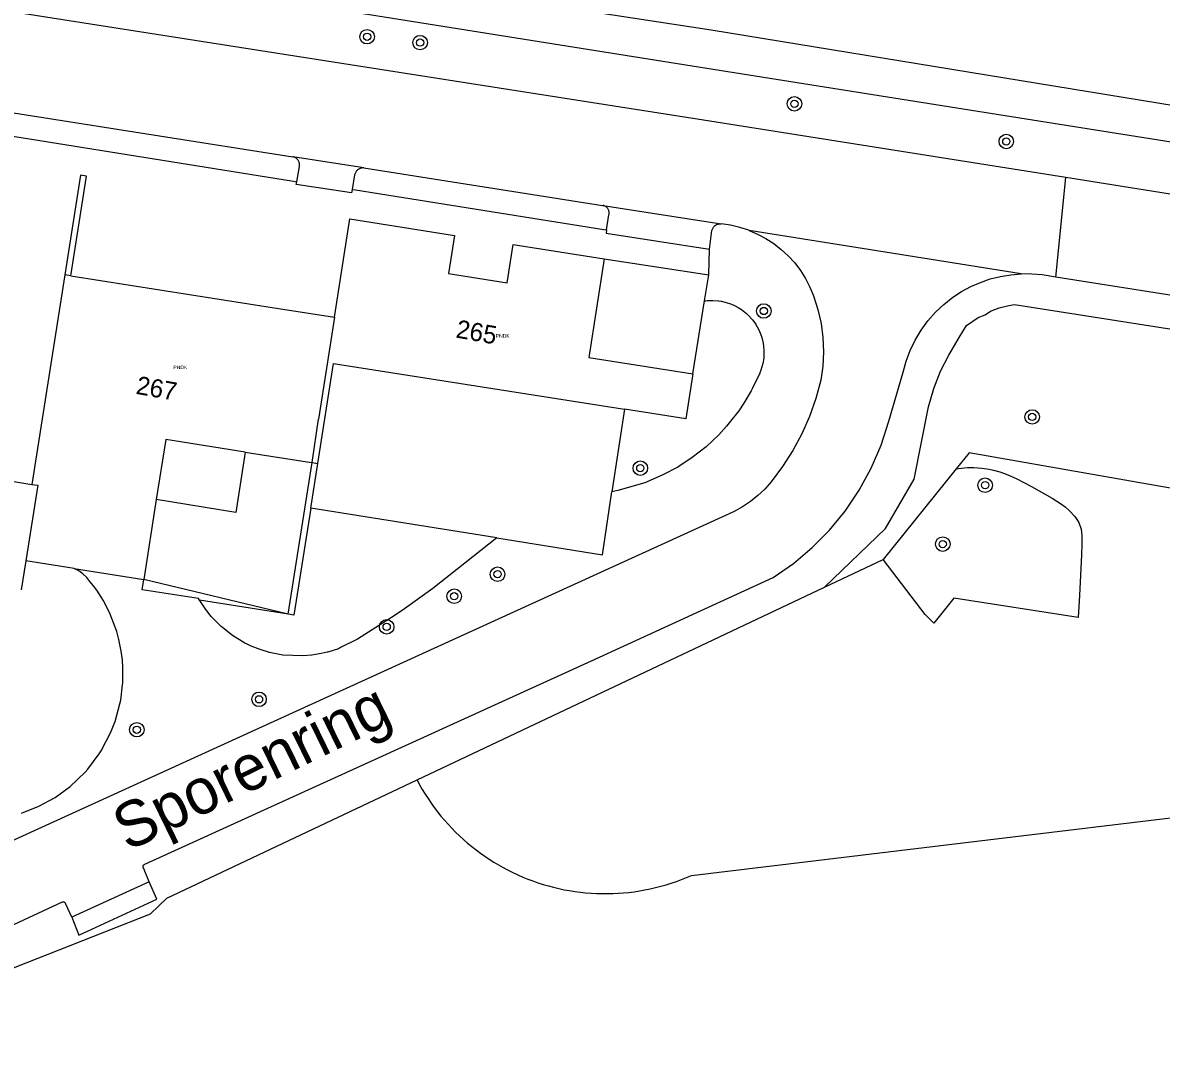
# Model space of a CAD drawing. Extents: x 131000 to 133013, y 393000 to 396501.
# Drawn here: x 132762.8 to 132825.5, y 394210.9 to 394268.4 of the extents above; entities that cross this region are included whole.
import ezdxf

# ---------------------------------------------------------------- set-up
doc = ezdxf.new("R2010")
doc.units = 0
for name, color, linetype in [('gg-anno-huisnummerreeks BGT', 7, 'Continuous'), ('gg-anno-openbare ruimte label', 7, 'Continuous'), ('gg-kwrk-kunstwerk niveau 01', 7, 'Continuous'), ('gt-symb-boom', 7, 'Continuous'), ('gx-grn-maaiveld', 7, 'Continuous'), ('kenmerkpunt-x pandkandidaat', 7, 'Continuous')]:
    doc.layers.add(name, color=color, linetype=linetype)

# ---------------------------------------------------------------- blocks, each defined once
blk = doc.blocks.new('gt0-BOOM')
at = {"layer": 'gt-symb-boom'}
for radius in [0.4, 0.2]:
    blk.add_circle((0, 0), radius, dxfattribs=at)

msp = doc.modelspace()

# ---------------------------------------------------------------- linework, layer by layer
at = {"layer": 'gg-kwrk-kunstwerk niveau 01'}
for p, q in [((132794.792, 394255.438), (132800.552, 394254.557)), ((132800.32, 394253.123), (132800.552, 394254.557)), ((132799.667, 394249.103), (132800.32, 394253.123))]:
    msp.add_line(p, q, dxfattribs=at)
for points in [[(132794.792, 394255.438), (132793.937, 394250.005), (132799.667, 394249.103)], [(132775.023, 394244.803), (132770.646, 394245.492), (132770.126, 394242.182)], [(132775.023, 394244.803), (132774.501, 394241.467), (132770.126, 394242.182)]]:
    msp.add_lwpolyline(points, dxfattribs=at)
at = {"layer": 'gx-grn-maaiveld'}
for p, q in [((132762.259, 394263.486), (132777.637, 394261.067)), ((132781.55, 394260.446), (132777.637, 394261.067)), ((132819.657, 394254.437), (132820.212, 394259.915)), ((132826.299, 394258.951), (132820.212, 394259.915)), ((132794.732, 394258.378), (132801.231, 394257.37)), ((132817.752, 394254.61), (132802.765, 394257.008)), ((132800.552, 394254.557), (132800.58, 394255.973)), ((132765.095, 394254.562), (132763.28, 394243.024)), ((132765.411, 394254.513), (132765.095, 394254.562)), ((132830.081, 394252.795), (132819.657, 394254.437)), ((132779.933, 394252.228), (132779.05, 394246.617)), ((132795.91, 394247.166), (132795.217, 394242.621)), ((132778.704, 394244.224), (132779.05, 394246.617)), ((132756.355, 394244.114), (132763.28, 394243.024)), ((132777.391, 394235.877), (132778.704, 394244.224)), ((132778.633, 394241.715), (132779.02, 394244.175)), ((132778.704, 394244.224), (132779.02, 394244.175)), ((132814.179, 394243.879), (132810.154, 394238.888)), ((132770.126, 394242.182), (132769.435, 394237.793)), ((132788.877, 394240.077), (132778.633, 394241.715)), ((132762.935, 394238.816), (132762.683, 394237.216)), ((132765.604, 394238.396), (132762.935, 394238.816)), ((132806.928, 394237.362), (132810.154, 394238.888)), ((132765.604, 394238.396), (132769.435, 394237.793)), ((132777.391, 394235.877), (132769.435, 394237.793)), ((132784.483, 394226.745), (132806.928, 394237.362)), ((132777.391, 394235.877), (132772.501, 394236.65)), ((132769.739, 394221.139), (132765.469, 394219.187))]:
    msp.add_line(p, q, dxfattribs=at)
for points in [[(132756.624, 394274.795), (132800.677, 394268.056), (132833.81, 394262.63)], [(132827.168, 394261.677), (132800.437, 394265.921), (132762.945, 394271.904)], [(132820.212, 394259.915), (132799.908, 394263.131), (132762.861, 394268.939)], [(132761.631, 394262.295), (132761.775, 394262.271), (132777.688, 394259.717), (132777.861, 394259.686)], [(132777.861, 394259.686), (132778.015, 394260.533), (132778.019, 394260.573), (132778.019, 394260.612), (132778.017, 394260.652), (132778.01, 394260.692), (132778.001, 394260.73), (132777.988, 394260.768), (132777.973, 394260.805), (132777.954, 394260.84), (132777.932, 394260.873), (132777.908, 394260.905), (132777.881, 394260.935), (132777.851, 394260.962), (132777.82, 394260.987), (132777.786, 394261.009), (132777.751, 394261.028), (132777.714, 394261.044), (132777.676, 394261.057), (132777.637, 394261.067)], [(132765.411, 394254.513), (132766.274, 394259.995), (132765.958, 394260.045), (132765.095, 394254.562)], [(132781.55, 394260.446), (132781.509, 394260.448), (132781.469, 394260.446), (132781.429, 394260.44), (132781.389, 394260.432), (132781.35, 394260.419), (132781.313, 394260.404), (132781.277, 394260.385), (132781.242, 394260.364), (132781.21, 394260.339), (132781.18, 394260.312), (132781.152, 394260.283), (132781.127, 394260.252), (132781.105, 394260.218), (132781.086, 394260.183), (132781.07, 394260.146), (132781.057, 394260.108), (132781.047, 394260.069), (132780.91, 394259.267)], [(132781.55, 394260.446), (132794.697, 394258.384), (132794.732, 394258.378)], [(132780.91, 394259.267), (132780.877, 394259.071), (132777.835, 394259.54), (132777.861, 394259.686)], [(132780.91, 394259.267), (132781.093, 394259.234), (132794.766, 394257.055), (132794.916, 394257.03)], [(132794.916, 394257.03), (132795.045, 394257.861), (132795.054, 394257.895), (132795.059, 394257.93), (132795.062, 394257.966), (132795.061, 394258.001), (132795.058, 394258.036), (132795.051, 394258.071), (132795.042, 394258.105), (132795.029, 394258.138), (132795.014, 394258.17), (132794.996, 394258.201), (132794.974, 394258.231), (132794.951, 394258.258), (132794.925, 394258.283), (132794.896, 394258.306), (132794.866, 394258.326), (132794.835, 394258.343), (132794.802, 394258.358), (132794.767, 394258.37), (132794.732, 394258.378)], [(132779.933, 394252.228), (132780.784, 394257.641), (132786.544, 394256.735), (132786.213, 394254.631), (132789.453, 394254.122), (132789.784, 394256.226), (132794.792, 394255.438)], [(132802.765, 394257.008), (132803.232, 394256.808), (132803.693, 394256.563), (132804.131, 394256.279), (132804.543, 394255.959), (132804.928, 394255.602), (132805.28, 394255.213), (132805.597, 394254.795), (132805.877, 394254.351), (132806.116, 394253.885), (132806.315, 394253.399), (132806.558, 394252.652), (132806.732, 394251.886), (132806.835, 394251.107), (132806.867, 394250.322), (132806.827, 394249.536), (132806.715, 394248.758), (132806.441, 394247.751), (132806.093, 394246.767), (132805.672, 394245.812), (132805.178, 394244.886), (132804.615, 394244), (132803.987, 394243.159), (132803.638, 394242.767), (132803.258, 394242.405), (132802.849, 394242.076), (132802.412, 394241.782), (132801.951, 394241.526), (132801.471, 394241.309), (132791.884, 394236.941), (132757.307, 394221.168)], [(132794.916, 394257.03), (132794.889, 394256.855), (132800.58, 394255.973)], [(132800.58, 394255.973), (132800.72, 394257.003), (132800.731, 394257.044), (132800.746, 394257.083), (132800.765, 394257.121), (132800.786, 394257.157), (132800.811, 394257.191), (132800.838, 394257.223), (132800.868, 394257.252), (132800.901, 394257.279), (132800.937, 394257.303), (132800.976, 394257.324), (132801.016, 394257.342), (132801.058, 394257.355), (132801.1, 394257.365), (132801.144, 394257.37), (132801.187, 394257.372), (132801.231, 394257.37)], [(132802.765, 394257.008), (132802.753, 394257.012), (132802.255, 394257.174), (132801.747, 394257.293), (132801.231, 394257.37)], [(132765.411, 394254.513), (132776.861, 394252.711), (132779.933, 394252.228)], [(132769.739, 394221.139), (132769.414, 394221.905), (132769.409, 394221.917), (132769.404, 394221.929), (132769.401, 394221.941), (132769.399, 394221.953), (132769.398, 394221.966), (132769.398, 394221.979), (132769.399, 394221.991), (132769.401, 394222.004), (132769.405, 394222.016), (132769.409, 394222.028), (132769.415, 394222.04), (132769.421, 394222.051), (132769.428, 394222.061), (132769.437, 394222.071), (132769.446, 394222.08), (132769.456, 394222.088), (132769.466, 394222.095), (132769.477, 394222.101), (132769.489, 394222.106), (132769.501, 394222.11), (132794.088, 394233.312), (132804.092, 394237.895), (132805.209, 394238.667), (132806.25, 394239.54), (132807.204, 394240.506), (132808.065, 394241.556), (132808.836, 394242.702), (132809.495, 394243.915), (132810.037, 394245.185), (132810.456, 394246.501), (132811.258, 394249.194), (132811.422, 394249.805), (132811.641, 394250.399), (132811.914, 394250.97), (132812.238, 394251.513), (132812.61, 394252.025), (132813.028, 394252.5), (132813.488, 394252.935), (132813.985, 394253.326), (132814.468, 394253.641), (132814.975, 394253.916), (132815.503, 394254.147), (132816.049, 394254.332), (132816.608, 394254.472), (132817.177, 394254.565), (132817.752, 394254.61)], [(132819.657, 394254.437), (132818.903, 394254.555), (132818.329, 394254.606), (132817.752, 394254.61)], [(132800.32, 394253.123), (132800.385, 394253.131), (132800.471, 394253.14), (132800.771, 394253.151), (132800.777, 394253.151), (132801.086, 394253.129), (132801.092, 394253.128), (132801.104, 394253.126), (132801.237, 394253.105), (132801.252, 394253.103), (132801.565, 394253.025), (132801.685, 394252.986), (132801.797, 394252.943), (132801.994, 394252.855), (132802.165, 394252.763), (132802.351, 394252.645), (132802.446, 394252.577), (132802.628, 394252.428), (132802.695, 394252.367), (132802.964, 394252.075), (132803.135, 394251.837), (132803.142, 394251.826), (132803.148, 394251.817), (132803.289, 394251.56), (132803.398, 394251.321), (132803.468, 394251.118), (132803.531, 394250.87), (132803.566, 394250.662), (132803.589, 394250.345), (132803.575, 394249.979), (132803.527, 394249.679), (132803.421, 394249.309), (132803.367, 394249.171), (132803.36, 394249.153), (132803.355, 394249.142), (132802.944, 394248.281), (132802.885, 394248.171), (132802.478, 394247.486), (132802.201, 394247.076), (132801.666, 394246.416), (132801.533, 394246.226), (132801.104, 394245.759), (132800.4, 394245.098), (132799.642, 394244.501), (132798.838, 394243.975), (132797.99, 394243.521), (132797.021, 394243.113), (132795.537, 394242.68), (132795.217, 394242.621)], [(132806.928, 394237.362), (132810.278, 394240.598), (132811.865, 394243.307), (132812.648, 394247.287), (132812.945, 394248.303), (132813.304, 394249.255), (132813.77, 394250.144), (132814.342, 394251.118), (132814.744, 394251.774), (132815.379, 394252.218), (132815.76, 394252.366), (132816.056, 394252.557), (132816.543, 394252.748), (132817.072, 394252.875), (132817.376, 394252.935), (132829.793, 394250.98)], [(132779.02, 394244.175), (132779.887, 394249.687), (132795.91, 394247.166)], [(132799.667, 394249.103), (132799.279, 394246.636), (132795.91, 394247.166)], [(132775.023, 394244.803), (132778.674, 394244.229), (132778.704, 394244.224)], [(132828.426, 394242.383), (132826.604, 394242.702), (132825.126, 394242.96), (132814.882, 394244.751), (132814.179, 394243.879)], [(132814.179, 394243.879), (132814.308, 394243.904), (132814.803, 394243.955), (132815.15, 394243.957), (132815.581, 394243.924), (132815.98, 394243.86), (132816.226, 394243.806), (132816.579, 394243.707), (132816.825, 394243.624), (132817.151, 394243.498), (132817.476, 394243.352), (132818.321, 394242.904), (132819.466, 394242.272), (132819.974, 394241.937), (132820.166, 394241.791), (132820.42, 394241.57), (132820.705, 394241.255), (132820.917, 394240.921), (132821.051, 394240.561), (132821.097, 394240.207), (132821.09, 394239.727), (132821.072, 394239.144), (132820.956, 394236.904), (132820.881, 394235.69), (132814.039, 394236.753), (132812.945, 394235.373), (132812.473, 394235.862), (132810.154, 394238.888)], [(132763.28, 394243.024), (132763.593, 394242.975), (132762.935, 394238.816)], [(132788.877, 394240.077), (132794.687, 394239.148), (132795.217, 394242.621)], [(132778.633, 394241.715), (132777.707, 394235.827), (132777.391, 394235.877)], [(132788.877, 394240.077), (132785.361, 394237.285), (132783.791, 394236.176), (132783.281, 394235.829), (132782.365, 394235.23), (132782.219, 394235.136), (132781.207, 394234.502), (132780.277, 394234.033), (132780.16, 394233.974), (132779.571, 394233.782), (132779.54, 394233.776), (132779.201, 394233.705), (132778.684, 394233.62), (132778.187, 394233.579), (132777.102, 394233.625), (132776.359, 394233.768), (132775.847, 394233.922), (132775.341, 394234.122), (132775.125, 394234.224), (132775.004, 394234.285), (132774.317, 394234.701), (132773.702, 394235.189), (132773.149, 394235.752), (132772.846, 394236.13), (132772.516, 394236.624), (132772.501, 394236.65)], [(132762.706, 394224.925), (132763.654, 394225.296), (132764.548, 394225.784), (132765.373, 394226.382), (132766.209, 394227.18), (132766.357, 394227.348), (132766.986, 394228.187), (132767.091, 394228.351), (132767.628, 394229.378), (132767.813, 394229.843), (132767.857, 394229.968), (132768.122, 394230.93), (132768.163, 394231.141), (132768.271, 394231.983), (132768.278, 394232.089), (132768.287, 394232.889), (132768.287, 394232.896), (132768.287, 394232.908), (132768.287, 394232.916), (132768.285, 394232.942), (132768.255, 394233.362), (132768.193, 394233.841), (132768.066, 394234.476), (132767.945, 394234.919), (132767.585, 394235.878), (132767.302, 394236.446), (132767.206, 394236.639), (132766.85, 394237.194), (132766.658, 394237.438), (132766.474, 394237.671), (132766.295, 394237.894), (132766.087, 394238.091), (132765.856, 394238.26), (132765.604, 394238.396)], [(132772.501, 394236.65), (132772.453, 394236.732), (132769.345, 394237.22), (132769.435, 394237.793)], [(132720.92, 394214.73), (132721.151, 394214.648), (132722.969, 394214), (132727.328, 394212.937), (132735.56, 394210.929), (132744.319, 394211.239), (132755.389, 394213.7), (132769.81, 394219.381), (132770.709, 394220.23), (132784.483, 394226.745)], [(132784.483, 394226.745), (132784.625, 394226.483), (132784.774, 394226.224), (132784.93, 394225.97), (132785.092, 394225.719), (132785.26, 394225.472), (132785.435, 394225.23), (132785.615, 394224.993), (132785.802, 394224.76), (132785.995, 394224.531), (132786.193, 394224.308), (132786.397, 394224.09), (132786.606, 394223.877), (132786.821, 394223.67), (132787.041, 394223.468), (132787.266, 394223.272), (132787.496, 394223.082), (132787.73, 394222.897), (132787.97, 394222.719), (132788.214, 394222.547), (132788.462, 394222.381), (132788.714, 394222.221), (132788.97, 394222.068), (132789.23, 394221.921), (132789.494, 394221.782), (132789.761, 394221.649), (132790.032, 394221.522), (132790.305, 394221.403), (132790.582, 394221.291), (132790.861, 394221.186), (132791.143, 394221.087), (132791.428, 394220.997), (132791.714, 394220.913), (132792.003, 394220.837), (132792.293, 394220.768), (132792.585, 394220.706), (132792.879, 394220.652), (132793.174, 394220.606), (132793.47, 394220.567), (132793.767, 394220.535), (132794.064, 394220.512), (132794.362, 394220.495), (132794.661, 394220.487), (132794.959, 394220.486), (132795.257, 394220.492), (132795.556, 394220.506), (132795.853, 394220.528), (132796.15, 394220.557), (132796.447, 394220.594), (132796.742, 394220.639), (132797.036, 394220.691), (132797.328, 394220.75), (132797.619, 394220.817), (132797.908, 394220.891), (132798.196, 394220.973), (132798.481, 394221.062), (132798.763, 394221.158), (132799.043, 394221.261), (132799.321, 394221.371), (132799.595, 394221.489), (132843.516, 394226.78)], [(132765.469, 394219.187), (132765.857, 394218.203), (132770.148, 394220.181), (132769.739, 394221.139)], [(132765.469, 394219.187), (132765.147, 394219.913), (132765.144, 394219.925), (132765.139, 394219.937), (132765.134, 394219.948), (132765.127, 394219.959), (132765.12, 394219.969), (132765.111, 394219.978), (132765.102, 394219.987), (132765.093, 394219.995), (132765.082, 394220.002), (132765.071, 394220.008), (132765.06, 394220.013), (132765.048, 394220.017), (132765.036, 394220.02), (132765.024, 394220.022), (132765.011, 394220.023), (132764.999, 394220.023), (132764.986, 394220.021), (132764.974, 394220.019), (132764.962, 394220.016), (132764.95, 394220.011), (132760.397, 394217.912)]]:
    msp.add_lwpolyline(points, dxfattribs=at)

# ---------------------------------------------------------------- block references
at = {"layer": 'gt-symb-boom'}
for p in [(132781.735, 394267.672), (132784.652, 394267.348), (132805.264, 394263.978), (132816.932, 394261.903), (132803.579, 394252.569), (132818.358, 394246.735), (132796.778, 394243.915), (132815.765, 394242.976), (132813.432, 394239.735), (132788.919, 394238.076), (132786.531, 394236.863), (132782.81, 394235.177), (132775.782, 394231.187), (132769.053, 394229.514)]:
    msp.add_blockref('gt0-BOOM', p, dxfattribs=at)

# ---------------------------------------------------------------- texts
at = {"layer": 'gg-anno-huisnummerreeks BGT'}
for s, p in [('265', (132786.579, 394251.114)), ('267', (132768.962, 394248.014))]:
    msp.add_text(s, height=1, rotation=350, dxfattribs=at).set_placement(p)
at = {"layer": 'gg-anno-openbare ruimte label'}
msp.add_text('Sporenring', height=2.5, rotation=26, dxfattribs=at).set_placement((132768.545, 394222.789))
at = {"layer": 'kenmerkpunt-x pandkandidaat'}
for p in [(132788.815, 394251.094), (132771.063, 394249.367)]:
    msp.add_text('PNDK', height=0.2, dxfattribs=at).set_placement(p)

doc.saveas('drawing.dxf')
